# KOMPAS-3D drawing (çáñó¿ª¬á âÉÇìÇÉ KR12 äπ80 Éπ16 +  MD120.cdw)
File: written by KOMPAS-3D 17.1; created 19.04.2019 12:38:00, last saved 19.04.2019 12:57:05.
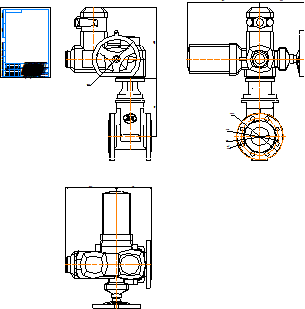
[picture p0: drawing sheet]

Sheet 1: A4, portrait

Title block, sheet 1: name: Задвижка ГРАНАР KR12 Ду80 Ру16 + / MD120; material: Внимание! Данный продукт является объектом авторского права ООО «Торговый Дом АДЛ». / Запрещается изменение, копирование, распространение / (в том числе путем копирования на другие сайты и ресурсы в Интернете) / или любое иное использование информации и объектов без предварительного / согласия правообладателя (ООО «Торговый Дом АДЛ»).; mass: 106,62; sheets: 1; organisation: ООО "Торговый дом АДЛ"; sheet format: A4; stored path: \\adlc.lan\data\АДЛ_ПКД\3D-модели\ADL production\Клиновые задвижки серии KR ГРАНАР\Клиновые задвижки KR12 с эл.приводами Смартгир\KOMPAS 2D\Задвижка ГРАНАР KR12 Ду80 Ру16 +  MD120.cdw

Views: Вид 1, Проекционный вид 2, Проекционный вид 4
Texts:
  user
Dimensions and other numbers on the sheet: 248; 299; 205; 308; 187; 200; 160; 80; 19; 8 Отв.; 214; 148; 1:1; 1; 106,62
